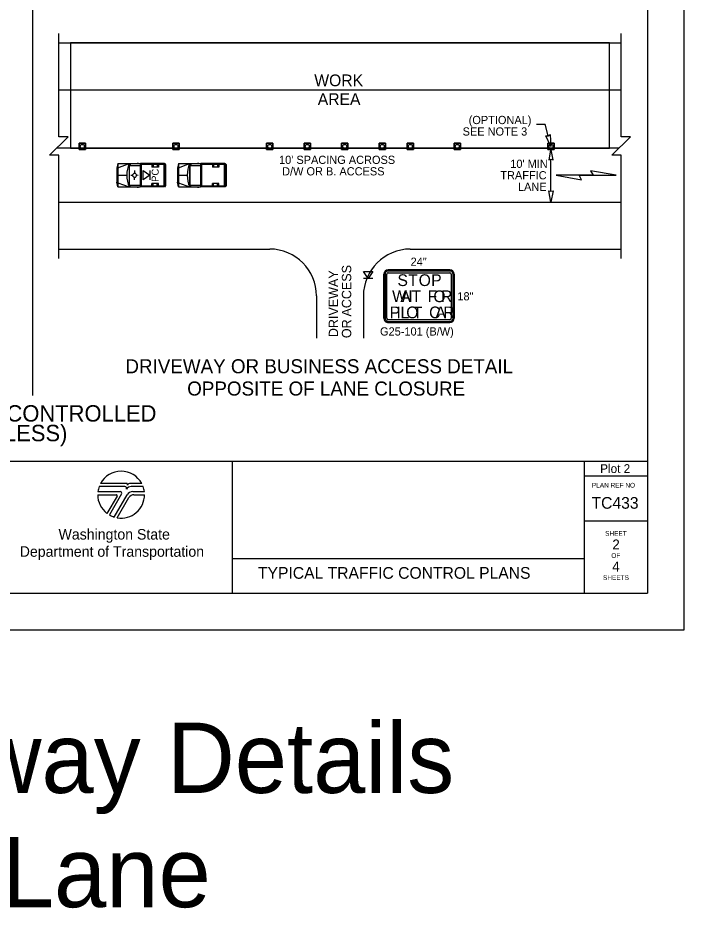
# Model space of a CAD drawing. Extents: x 99999.1 to 100095.7, y 99995 to 100010.7.
# Drawn here: x 100030.38 to 100036.06, y 99997.31 to 100004.91 of the extents above; entities that cross this region are included whole.
import ezdxf

# ---------------------------------------------------------------- set-up
doc = ezdxf.new("R2010")
doc.units = 0
for name, color, linetype in [('RD_ED_DrivewayEdge', 7, 'Continuous'), ('RD_ED_ShoulderPavedEdge', 7, 'Continuous'), ('RD_MK_LineEdgeWhite', 7, 'Continuous'), ('RD_MK_LineSkipCenter', 7, 'Continuous'), ('SH_DE_DetailHeading1Text', 7, 'Continuous'), ('SH_DE_DetailHeading2Text', 7, 'Continuous'), ('SH_GI_PlotLimits', 7, 'Continuous'), ('SH_GI_SheetBorder', 7, 'Continuous'), ('SH_GI_SheetLocationText', 7, 'Continuous'), ('SH_GI_SheetTextInCells', 7, 'Continuous'), ('SH_GI_TitleBlockText', 7, 'Continuous'), ('SH_GI_WSDOTLogo', 7, 'Continuous'), ('TR_SN_ConstructionSigns', 7, 'Continuous'), ('TR_WZ_MotoristVehicle', 7, 'Continuous'), ('TR_WZ_PortableSignMountBlk-Wht', 7, 'Continuous'), ('TR_WZ_TrafficCone', 7, 'Continuous'), ('TR_WZ_WorkAreaLabel', 7, 'Continuous'), ('TR_WZ_WorkZoneDetails', 7, 'Continuous'), ('TR_WZ_WorkZoneTextCurrent', 7, 'Continuous')]:
    doc.layers.add(name, color=color, linetype=linetype)

msp = doc.modelspace()

# ---------------------------------------------------------------- linework, layer by layer
at = {"layer": 'RD_ED_DrivewayEdge'}
for p, q in [((100032.925, 100002.5359), (100032.925, 100002.1759)), ((100033.325, 100002.5359), (100033.325, 100002.1759))]:
    msp.add_line(p, q, dxfattribs=at)
for centre, start, end in [((100032.525, 100002.5359), 0, 90), ((100033.725, 100002.5359), 90, 180)]:
    msp.add_arc(centre, 0.4, start, end, dxfattribs=at)
at = {"layer": 'RD_ED_ShoulderPavedEdge'}
for p, q in [((100030.725, 100004.6959), (100035.525, 100004.6959)), ((100030.725, 100002.9359), (100032.525, 100002.9359)), ((100033.725, 100002.9359), (100035.525, 100002.9359))]:
    msp.add_line(p, q, dxfattribs=at)
at = {"layer": 'RD_MK_LineEdgeWhite'}
for p, q in [((100030.725, 100004.2959), (100035.525, 100004.2959)), ((100030.725, 100003.3359), (100035.525, 100003.3359))]:
    msp.add_line(p, q, dxfattribs=at)
at = {"layer": 'RD_MK_LineSkipCenter'}
msp.add_lwpolyline([(100035.5043, 100003.7959), (100030.7043, 100003.7959)], dxfattribs=at)
at = {"layer": 'SH_GI_PlotLimits'}
msp.add_lwpolyline([(100019.0625, 99999.6875), (100036.0625, 99999.6875), (100036.0625, 100010.6875), (100019.0625, 100010.6875)], close=True, dxfattribs=at)
at = {"layer": 'SH_GI_SheetBorder'}
for p, q in [((100035.75, 100010.375), (100035.75, 100000)), ((100020, 100001.1259), (100035.75, 100001.1259)), ((100032.2055, 100001.1259), (100032.2055, 100000)), ((100035.2079, 100001.1259), (100035.2079, 100000)), ((100035.2079, 100001.0008), (100035.75, 100001.0008)), ((100035.2079, 100000.6176), (100035.75, 100000.6176)), ((100032.2055, 100000.2955), (100035.2079, 100000.2955)), ((100020, 100000), (100035.75, 100000))]:
    msp.add_line(p, q, dxfattribs=at)
at = {"layer": 'SH_GI_WSDOTLogo'}
for p, q in [((100031.2894, 100000.9094), (100031.0697, 100000.9094)), ((100031.303, 100000.9354), (100031.0815, 100000.9354)), ((100031.433, 100000.9354), (100031.3351, 100000.9354)), ((100031.343, 100000.9094), (100031.3429, 100000.9094)), ((100031.4448, 100000.9094), (100031.343, 100000.9094)), ((100031.0572, 100000.84), (100031.2148, 100000.84)), ((100031.059, 100000.8661), (100031.2496, 100000.8661)), ((100031.222, 100000.8277), (100031.1364, 100000.6807)), ((100031.261, 100000.8464), (100031.1567, 100000.6672)), ((100031.1989, 100000.6487), (100031.3089, 100000.839)), ((100031.3558, 100000.8661), (100031.4555, 100000.8661)), ((100031.3655, 100000.8394), (100031.4572, 100000.8394)), ((100031.2244, 100000.6428), (100031.3242, 100000.8156))]:
    msp.add_line(p, q, dxfattribs=at)
for centre, radius, start, end in [((100031.2572, 100000.84), 0.2, 28.47865, 151.53204), ((100031.2572, 100000.84), 0.2, 159.69598, 172.50569), ((100031.2894, 100000.8946), 0.0148, 327.8418, 89.99855), ((100031.3429, 100000.861), 0.0484, 89.99529, 147.82376), ((100031.303, 100000.9263), 0.00903, 329.87418, 90.00328), ((100031.3352, 100000.9066), 0.0287, 90.00721, 148.16763), ((100031.2572, 100000.84), 0.2, 7.49431, 20.29406), ((100031.2572, 100000.84), 0.2, 179.99864, 232.84327), ((100031.2149, 100000.8318), 0.0082, 329.74356, 90), ((100031.2572, 100000.84), 0.2, 260.54554, 359.80857), ((100031.2497, 100000.853), 0.0131, 329.76834, 90), ((100031.3558, 100000.8119), 0.0542, 90, 149.99738), ((100031.3654, 100000.7918), 0.0476, 90, 150.05432), ((100031.2572, 100000.84), 0.2, 239.79292, 253.0448)]:
    msp.add_arc(centre, radius, start, end, dxfattribs=at)
at = {"layer": 'TR_SN_ConstructionSigns'}
for p, q in [((100033.5, 100002.3456), (100033.5, 100002.7206)), ((100033.5, 100002.7206), (100033.5, 100002.3456)), ((100033.5094, 100002.7206), (100033.5094, 100002.3456)), ((100033.525, 100002.3456), (100033.525, 100002.7206)), ((100033.5375, 100002.7581), (100034.0625, 100002.7581)), ((100034.0625, 100002.7581), (100033.5375, 100002.7581)), ((100034.0625, 100002.7488), (100033.5375, 100002.7488)), ((100033.5375, 100002.7331), (100034.0625, 100002.7331)), ((100034.075, 100002.7206), (100034.075, 100002.3456)), ((100034.0906, 100002.3456), (100034.0906, 100002.7206)), ((100034.1, 100002.7206), (100034.1, 100002.3456)), ((100034.1, 100002.3456), (100034.1, 100002.7206)), ((100034.0625, 100002.3331), (100033.5375, 100002.3331)), ((100033.5375, 100002.3175), (100034.0625, 100002.3175)), ((100034.0625, 100002.3081), (100033.5375, 100002.3081)), ((100033.5375, 100002.3081), (100034.0625, 100002.3081))]:
    msp.add_line(p, q, dxfattribs=at)
for centre, radius, start, end in [((100033.5375, 100002.7206), 0.0375, 90, 180), ((100033.5375, 100002.7206), 0.0375, 90, 180), ((100033.5375, 100002.7206), 0.0281, 90, 180.00001), ((100033.5375, 100002.7206), 0.0125, 90, 180.00001), ((100034.0625, 100002.7206), 0.0375, 0, 90), ((100034.0625, 100002.7206), 0.0375, 0, 90), ((100034.0625, 100002.7206), 0.0281, 0, 90), ((100034.0625, 100002.7206), 0.0125, 0, 90), ((100033.5375, 100002.3456), 0.0375, 180, 270.00001), ((100033.5375, 100002.3456), 0.0375, 180, 270.00001), ((100033.5375, 100002.3456), 0.0281, 180.00001, 270), ((100033.5375, 100002.3456), 0.0125, 180.00001, 270), ((100034.0625, 100002.3456), 0.0375, 270.00001, 0.00001), ((100034.0625, 100002.3456), 0.0375, 270.00001, 0.00001), ((100034.0625, 100002.3456), 0.0281, 270, 0.00001), ((100034.0625, 100002.3456), 0.0125, 270, 0.00001)]:
    msp.add_arc(centre, radius, start, end, dxfattribs=at)
at = {"layer": 'TR_WZ_MotoristVehicle'}
for p, q in [((100031.23, 100003.6659), (100031.2207, 100003.6255)), ((100031.23, 100003.6659), (100031.23, 100003.4659)), ((100031.23, 100003.6659), (100031.4189, 100003.6659)), ((100031.23, 100003.6293), (100031.3245, 100003.6659)), ((100031.3245, 100003.6659), (100031.3245, 100003.4659)), ((100031.3262, 100003.6659), (100031.3262, 100003.4659)), ((100031.3262, 100003.6659), (100031.3382, 100003.6504)), ((100031.3262, 100003.6504), (100031.4189, 100003.6504)), ((100031.3932, 100003.6687), (100031.4045, 100003.6687)), ((100031.4189, 100003.6659), (100031.4189, 100003.4659)), ((100031.6274, 100003.6659), (100031.4217, 100003.6659)), ((100031.4217, 100003.6659), (100031.4217, 100003.4659)), ((100031.6215, 100003.6579), (100031.4275, 100003.6579)), ((100031.4275, 100003.6579), (100031.4275, 100003.4739)), ((100031.5202, 100003.6579), (100031.5202, 100003.6349)), ((100031.5752, 100003.6349), (100031.5202, 100003.6349)), ((100031.5302, 100003.6579), (100031.5302, 100003.6349)), ((100031.5642, 100003.6579), (100031.5642, 100003.6349)), ((100031.5752, 100003.6579), (100031.5752, 100003.6349)), ((100031.6215, 100003.6579), (100031.6215, 100003.4739)), ((100031.6274, 100003.6659), (100031.6274, 100003.4659)), ((100031.6325, 100003.6626), (100031.6281, 100003.6626)), ((100031.6281, 100003.6626), (100031.6281, 100003.4692)), ((100031.637, 100003.6565), (100031.637, 100003.4753)), ((100031.7463, 100003.6659), (100031.737, 100003.6255)), ((100031.7463, 100003.6659), (100031.7463, 100003.4659)), ((100031.7463, 100003.6659), (100031.9352, 100003.6659)), ((100031.7463, 100003.6293), (100031.8407, 100003.6659)), ((100031.8407, 100003.6659), (100031.8407, 100003.4659)), ((100031.8424, 100003.6659), (100031.8424, 100003.4659)), ((100031.8424, 100003.6659), (100031.8545, 100003.6504)), ((100031.8424, 100003.6504), (100031.9352, 100003.6504)), ((100031.9094, 100003.6687), (100031.9207, 100003.6687)), ((100031.9352, 100003.6659), (100031.9352, 100003.4659)), ((100032.1436, 100003.6659), (100031.9379, 100003.6659)), ((100031.9379, 100003.6659), (100031.9379, 100003.4659)), ((100032.1378, 100003.6579), (100031.9438, 100003.6579)), ((100031.9438, 100003.6579), (100031.9438, 100003.4739)), ((100032.0365, 100003.6579), (100032.0365, 100003.6349)), ((100032.0914, 100003.6349), (100032.0365, 100003.6349)), ((100032.0465, 100003.6579), (100032.0465, 100003.6349)), ((100032.0805, 100003.6579), (100032.0805, 100003.6349)), ((100032.0914, 100003.6579), (100032.0914, 100003.6349)), ((100032.1378, 100003.6579), (100032.1378, 100003.4739)), ((100032.1436, 100003.6659), (100032.1436, 100003.4659)), ((100032.1488, 100003.6626), (100032.1443, 100003.6626)), ((100032.1443, 100003.6626), (100032.1443, 100003.4692)), ((100032.1533, 100003.6565), (100032.1533, 100003.4753)), ((100031.2207, 100003.6255), (100031.2207, 100003.5063)), ((100031.23, 100003.5659), (100031.3059, 100003.5659)), ((100031.3414, 100003.566), (100031.354, 100003.566)), ((100031.3715, 100003.6055), (100031.3715, 100003.5894)), ((100031.3856, 100003.5656), (100031.3856, 100003.5656)), ((100031.4024, 100003.5651), (100031.3875, 100003.5655)), ((100031.637, 100003.58), (100031.6281, 100003.5762)), ((100031.637, 100003.5518), (100031.6281, 100003.5556)), ((100031.6346, 100003.5659), (100031.6305, 100003.5659)), ((100031.6325, 100003.5687), (100031.6325, 100003.5631)), ((100031.737, 100003.6255), (100031.737, 100003.5063)), ((100031.7463, 100003.5659), (100031.8222, 100003.5659)), ((100032.1533, 100003.58), (100032.1443, 100003.5762)), ((100032.1533, 100003.5518), (100032.1443, 100003.5556)), ((100032.1509, 100003.5659), (100032.1467, 100003.5659)), ((100032.1488, 100003.5687), (100032.1488, 100003.5631)), ((100031.23, 100003.4659), (100031.2207, 100003.5063)), ((100031.23, 100003.5025), (100031.3245, 100003.4659)), ((100031.3262, 100003.4814), (100031.4189, 100003.4814)), ((100031.3361, 100003.4814), (100031.3262, 100003.4659)), ((100031.3722, 100003.5274), (100031.3719, 100003.5425)), ((100031.5202, 100003.4739), (100031.5202, 100003.4969)), ((100031.5752, 100003.4969), (100031.5202, 100003.4969)), ((100031.5302, 100003.4739), (100031.5302, 100003.4969)), ((100031.5642, 100003.4739), (100031.5642, 100003.4969)), ((100031.5752, 100003.4739), (100031.5752, 100003.4969)), ((100031.7463, 100003.4659), (100031.737, 100003.5063)), ((100031.7463, 100003.5025), (100031.8407, 100003.4659)), ((100031.8424, 100003.4814), (100031.9352, 100003.4814)), ((100031.8524, 100003.4814), (100031.8424, 100003.4659)), ((100032.0365, 100003.4739), (100032.0365, 100003.4969)), ((100032.0914, 100003.4969), (100032.0365, 100003.4969)), ((100032.0465, 100003.4739), (100032.0465, 100003.4969)), ((100032.0805, 100003.4739), (100032.0805, 100003.4969)), ((100032.0914, 100003.4739), (100032.0914, 100003.4969)), ((100031.23, 100003.4659), (100031.4189, 100003.4659)), ((100031.3932, 100003.4631), (100031.4045, 100003.4631)), ((100031.6274, 100003.4659), (100031.4217, 100003.4659)), ((100031.6215, 100003.4739), (100031.4275, 100003.4739)), ((100031.6325, 100003.4692), (100031.6281, 100003.4692)), ((100031.7463, 100003.4659), (100031.9352, 100003.4659)), ((100031.9094, 100003.4631), (100031.9207, 100003.4631)), ((100032.1436, 100003.4659), (100031.9379, 100003.4659)), ((100032.1378, 100003.4739), (100031.9438, 100003.4739)), ((100032.1488, 100003.4692), (100032.1443, 100003.4692))]:
    msp.add_line(p, q, dxfattribs=at)
for centre, major_axis, start_param, end_param in [((100031.4595, 100003.5659), (0, -0.2099), 4.215667, 5.208926), ((100031.6325, 100003.6565), (0, 0.0061), 4.712389, 6.283185), ((100031.9757, 100003.5659), (0, -0.2099), 4.215667, 5.208926), ((100032.1488, 100003.6565), (0, 0.0061), 4.712389, 6.283185), ((100031.6325, 100003.4753), (0, -0.0061), 0, 1.570796), ((100032.1488, 100003.4753), (0, -0.0061), 0, 1.570796)]:
    msp.add_ellipse(centre, major_axis=major_axis, ratio=0.73155, start_param=start_param, end_param=end_param, dxfattribs=at)
for centre, major_axis in [((100031.3715, 100003.5659), (0, 0.0193)), ((100031.6325, 100003.5659), (0, 0.00282)), ((100032.1488, 100003.5659), (0, 0.00282))]:
    msp.add_ellipse(centre, major_axis=major_axis, ratio=0.73155, dxfattribs=at)
at = {"layer": 'TR_WZ_PortableSignMountBlk-Wht'}
for p, q in [((100031.5013, 100003.6058), (100031.5013, 100003.5258)), ((100033.405, 100002.6859), (100033.325, 100002.6859))]:
    msp.add_line(p, q, dxfattribs=at)
for points in [[(100031.5013, 100003.5659), (100031.4439, 100003.5258), (100031.4439, 100003.6058)], [(100033.3651, 100002.6859), (100033.325, 100002.7434), (100033.405, 100002.7434)]]:
    msp.add_lwpolyline(points, close=True, dxfattribs=at)
at = {"layer": 'TR_WZ_TrafficCone'}
for points in [[(100030.899, 100003.8392), (100030.9524, 100003.8392), (100030.9524, 100003.7859), (100030.899, 100003.7859), (100030.899, 100003.8392)], [(100030.899, 100003.7859), (100030.9524, 100003.7859), (100030.9524, 100003.8392), (100030.899, 100003.8392), (100030.899, 100003.7859)], [(100031.699, 100003.8392), (100031.7524, 100003.8392), (100031.7524, 100003.7859), (100031.699, 100003.7859), (100031.699, 100003.8392)], [(100031.699, 100003.7859), (100031.7524, 100003.7859), (100031.7524, 100003.8392), (100031.699, 100003.8392), (100031.699, 100003.7859)], [(100032.499, 100003.8392), (100032.5524, 100003.8392), (100032.5524, 100003.7859), (100032.499, 100003.7859), (100032.499, 100003.8392)], [(100032.499, 100003.7859), (100032.5524, 100003.7859), (100032.5524, 100003.8392), (100032.499, 100003.8392), (100032.499, 100003.7859)], [(100032.819, 100003.8392), (100032.8723, 100003.8392), (100032.8723, 100003.7859), (100032.819, 100003.7859), (100032.819, 100003.8392)], [(100032.819, 100003.7859), (100032.8723, 100003.7859), (100032.8723, 100003.8392), (100032.819, 100003.8392), (100032.819, 100003.7859)], [(100033.139, 100003.8392), (100033.1923, 100003.8392), (100033.1923, 100003.7859), (100033.139, 100003.7859), (100033.139, 100003.8392)], [(100033.139, 100003.7859), (100033.1923, 100003.7859), (100033.1923, 100003.8392), (100033.139, 100003.8392), (100033.139, 100003.7859)], [(100033.459, 100003.8392), (100033.5123, 100003.8392), (100033.5123, 100003.7859), (100033.459, 100003.7859), (100033.459, 100003.8392)], [(100033.459, 100003.7859), (100033.5123, 100003.7859), (100033.5123, 100003.8392), (100033.459, 100003.8392), (100033.459, 100003.7859)], [(100033.6983, 100003.8392), (100033.7517, 100003.8392), (100033.7517, 100003.7859), (100033.6983, 100003.7859), (100033.6983, 100003.8392)], [(100033.6983, 100003.7859), (100033.7517, 100003.7859), (100033.7517, 100003.8392), (100033.6983, 100003.8392), (100033.6983, 100003.7859)], [(100034.099, 100003.8392), (100034.1524, 100003.8392), (100034.1524, 100003.7859), (100034.099, 100003.7859), (100034.099, 100003.8392)], [(100034.099, 100003.7859), (100034.1524, 100003.7859), (100034.1524, 100003.8392), (100034.099, 100003.8392), (100034.099, 100003.7859)], [(100034.899, 100003.8392), (100034.9524, 100003.8392), (100034.9524, 100003.7859), (100034.899, 100003.7859), (100034.899, 100003.8392)], [(100034.899, 100003.7859), (100034.9524, 100003.7859), (100034.9524, 100003.8392), (100034.899, 100003.8392), (100034.899, 100003.7859)]]:
    msp.add_lwpolyline(points, dxfattribs=at)
for centre in [(100030.9257, 100003.8126), (100031.7257, 100003.8126), (100032.5257, 100003.8126), (100032.8457, 100003.8126), (100033.1657, 100003.8126), (100033.4857, 100003.8126), (100033.725, 100003.8126), (100034.1257, 100003.8126), (100034.9257, 100003.8126)]:
    msp.add_circle(centre, 0.0167, dxfattribs=at)
at = {"layer": 'TR_WZ_WorkZoneDetails'}
for p, q in [((100030.5, 100010.275), (100030.5, 100001.6859)), ((100034.8007, 100004.0006), (100034.8769, 100004.0006)), ((100034.9022, 100003.9033), (100034.8769, 100004.0006)), ((100034.9256, 100003.4296), (100034.9256, 100003.7022)), ((100035.2856, 100003.5659), (100035.0445, 100003.5659)), ((100035.1651, 100003.5659), (100035.4062, 100003.5659)), ((100033.5, 100002.7206), (100033.5, 100002.3456)), ((100034.0625, 100002.7581), (100033.5375, 100002.7581)), ((100034.1, 100002.3456), (100034.1, 100002.7206)), ((100033.5375, 100002.3081), (100034.0625, 100002.3081))]:
    msp.add_line(p, q, dxfattribs=at)
for points in [[(100030.725, 100002.8559), (100030.725, 100003.7385), (100030.645, 100003.7385), (100030.805, 100003.8933), (100030.725, 100003.8933), (100030.725, 100004.7759)], [(100035.525, 100002.8559), (100035.525, 100003.7385), (100035.445, 100003.7385), (100035.605, 100003.8933), (100035.525, 100003.8933), (100035.525, 100004.7759)]]:
    msp.add_lwpolyline(points, dxfattribs=at)
for points in [[(100030.825, 100004.6959), (100030.825, 100003.7959), (100035.425, 100003.7959), (100035.425, 100004.6959)], [(100034.9257, 100003.8126), (100034.8824, 100003.9029), (100034.9022, 100003.9033), (100034.9197, 100003.9125)], [(100034.9257, 100003.7959), (100034.9064, 100003.6976), (100034.9257, 100003.7022), (100034.945, 100003.6976)], [(100034.9685, 100003.5659), (100035.1873, 100003.5273), (100035.1651, 100003.5659)], [(100035.4821, 100003.5659), (100035.2633, 100003.6045), (100035.2856, 100003.5659)], [(100034.9256, 100003.3359), (100034.9064, 100003.4342), (100034.9256, 100003.4296), (100034.9449, 100003.4342)]]:
    msp.add_lwpolyline(points, close=True, dxfattribs=at)
for centre, start, end in [((100033.5375, 100002.7206), 90, 180), ((100034.0625, 100002.7206), 0, 90), ((100033.5375, 100002.3456), 180, 270.00001), ((100034.0625, 100002.3456), 270.00001, 0.00001)]:
    msp.add_arc(centre, 0.0375, start, end, dxfattribs=at)

# ---------------------------------------------------------------- texts
at = {"layer": 'SH_DE_DetailHeading1Text'}
for s, p in [('PILOT CAR OPERATION FOR ALTERNATING 1-LANE, 2-WAY TRAFFIC: AFAD-CONTROLLED', (100023.4137, 100001.4639)), ('SHARED BIKE-VEHICLE LANE STRATEGY (HIGHWAYS, 40 MPH OR LESS)', (100024.2342, 100001.2959))]:
    msp.add_text(s, height=0.14, rotation=360, dxfattribs=at).set_placement(p)
at = {"layer": 'SH_DE_DetailHeading2Text'}
for s, p in [('DRIVEWAY OR BUSINESS ACCESS DETAIL', (100031.2936, 100001.8759)), ('OPPOSITE OF LANE CLOSURE', (100031.8211, 100001.6859))]:
    msp.add_text(s, height=0.12, rotation=360, dxfattribs=at).set_placement(p)
at = {"layer": 'SH_GI_SheetBorder'}
msp.add_text('PLAN REF NO', height=0.040032, dxfattribs=at).set_placement((100035.2747, 100000.9008))
at = {"layer": 'SH_GI_SheetLocationText'}
for s, height, p in [('Plot 2', 0.075, (100035.3454, 100001.025)), ('Access & Intersecting Roadway Details', 0.6, (100020.1422, 99998.2946)), ('Shared Bike-Vehicle Lane', 0.6, (100022.7454, 99997.3196))]:
    msp.add_text(s, height=height, dxfattribs=at).set_placement(p)
at = {"layer": 'SH_GI_SheetTextInCells'}
for s, height, p in [('Washington State', 0.090072, (100030.7229, 100000.4571)), ('SHEET', 0.04003, (100035.3877, 100000.4896)), ('Department of Transportation', 0.090072, (100030.3916, 100000.3101)), ('OF', 0.04003, (100035.4406, 100000.3008)), ('SHEETS', 0.04003, (100035.3698, 100000.112))]:
    msp.add_text(s, height=height, dxfattribs=at).set_placement(p)
at = {"layer": 'SH_GI_TitleBlockText'}
for s, height, p in [('TC433', 0.1, (100035.2718, 100000.72)), ('2', 0.085, (100035.4493, 100000.3723)), ('TYPICAL TRAFFIC CONTROL PLANS', 0.1, (100032.4251, 100000.1224)), ('4', 0.085, (100035.4485, 100000.1843))]:
    msp.add_text(s, height=height, dxfattribs=at).set_placement(p)
at = {"layer": 'TR_SN_ConstructionSigns'}
for s, p in [('24"', (100033.7276, 100002.7931)), ('18"', (100034.1269, 100002.4981)), ('G25-101 (B/W)', (100033.4667, 100002.1981))]:
    msp.add_text(s, height=0.07, rotation=360, dxfattribs=at).set_placement(p)
at = {"layer": 'TR_WZ_MotoristVehicle'}
msp.add_text('PC', height=0.06, rotation=90, dxfattribs=at).set_placement((100031.5777, 100003.5099))
at = {"layer": 'TR_WZ_WorkAreaLabel'}
for s, p in [('WORK', (100032.9058, 100004.3259)), ('AREA', (100032.9354, 100004.1659))]:
    msp.add_text(s, height=0.1, dxfattribs=at).set_placement(p)
at = {"layer": 'TR_WZ_WorkZoneDetails'}
for s, p in [('S', (100033.6155, 100002.6206)), ('T', (100033.7075, 100002.6206)), ('O', (100033.7965, 100002.6206)), ('P', (100033.9035, 100002.6206)), ('W', (100033.57, 100002.4831)), ('A', (100033.64, 100002.4831)), ('I', (100033.708, 100002.4831)), ('T', (100033.735, 100002.4831)), ('F', (100033.873, 100002.4831)), ('O', (100033.922, 100002.4831)), ('R', (100033.987, 100002.4831)), ('P', (100033.5495, 100002.3456)), ('I', (100033.6065, 100002.3456)), ('L', (100033.6415, 100002.3456)), ('O', (100033.6905, 100002.3456)), ('T', (100033.7475, 100002.3456)), ('C', (100033.8855, 100002.3456)), ('A', (100033.9395, 100002.3456)), ('R', (100034.0075, 100002.3456))]:
    msp.add_text(s, height=0.1, dxfattribs=at).set_placement(p)
at = {"layer": 'TR_WZ_WorkZoneTextCurrent'}
for s, p in [('(OPTIONAL)', (100034.2233, 100004.0026)), ('SEE NOTE 3', (100034.1716, 100003.9046)), ("10' SPACING ACROSS", (100032.605, 100003.6626)), ('D/W OR B. ACCESS', (100032.6312, 100003.5646)), ("10' MIN", (100034.5783, 100003.6289)), ('TRAFFIC', (100034.4933, 100003.5309)), ('LANE', (100034.6437, 100003.4329))]:
    msp.add_text(s, height=0.07, dxfattribs=at).set_placement(p)
for s, p in [('ACCESS', (100033.221, 100002.3602)), ('DRIVEWAY', (100033.109, 100002.1842)), ('OR', (100033.221, 100002.1759))]:
    msp.add_text(s, height=0.08, rotation=90, dxfattribs=at).set_placement(p)

doc.saveas('drawing.dxf')
